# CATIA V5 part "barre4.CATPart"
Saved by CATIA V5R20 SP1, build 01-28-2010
Part number: barre4
Publications: "Plan.1", "C", "B", "G", "axe_4_1", "axe_4_5"
Bounding box of the stored display mesh (mm): x -10 to 10, y -929.464 to -181.831, z 83.907 to 466.848
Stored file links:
  C:\Users\patrice\Desktop\IFMa\Semestre 3\IAO\projet iao\iao\barre4.CATPart
  C:\Users\patrice\Desktop\IFMa\Semestre 3\IAO\projet iao\iao\skl_iao_755.CATProduct
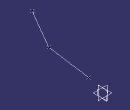
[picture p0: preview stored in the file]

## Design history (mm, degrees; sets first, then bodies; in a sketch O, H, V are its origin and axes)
Set1
  Plane1: linked copy from another document
  Point1 "C": linked copy from another document
  DatumPoint1 "B": linked copy from another document
  DatumPoint2 "G": linked copy from another document
Set2
  Plane2: type Offset, RefPlane Plane1, Offset 0
  Point2 "C": (0, 0, 0), relative to Point1
  Point3 "B": (0, 0, 0), relative to DatumPoint1
  Point4 "G": (0, 0, 0), relative to DatumPoint2
  Line1: type PtPt, FirstPoint Point2, SecondPoint Point3
  Line2: type PtPt, FirstPoint Point3, SecondPoint Point4
  Line3 "axe_4_1": type Normal, RefPoint Point2, RefSkin Plane2, Start 0, End 10
  Line4 "axe_4_5": type Normal, RefPoint Point4, RefSkin Plane2, Start 0, End 10
Body1 (main body)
